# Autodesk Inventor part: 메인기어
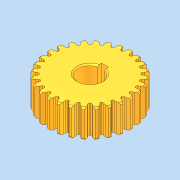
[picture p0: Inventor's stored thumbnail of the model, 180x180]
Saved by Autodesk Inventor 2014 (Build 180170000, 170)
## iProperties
Company: 한국ATC센터
Created: 2014-12
Part Number: 메인기어
Document SubType Name: Modeling
Designer: KYOUNG IL JANG
Density: 1 g/cm^3
Mass: 43.883 g
Surface Area: 122.661 cm^2
Volume: 43.883 cm^3
Material: 일반
Appearance: 금속 2400F 열
Author: KYOUNG IL JANG
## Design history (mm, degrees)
sketch "스케치1"
  geometry: C1 r 25.5 at (0, 0); A1 r 1.064 centre (-2.94, 26.392) between (-2.696, 25.357) and (-1.877, 26.361); A2 r 6.991 centre (5.094, 25.835) between (-1.626, 27.763) and (-1.877, 26.361); A3 r 11.864 centre (9.774, 24.478) between (-0.731, 29.991) and (-1.626, 27.763); A4 r 1.064 centre (2.94, 26.392) between (1.877, 26.361) and (2.696, 25.357); A5 r 6.991 centre (-5.094, 25.835) between (1.877, 26.361) and (1.626, 27.763); A6 r 11.864 centre (-9.774, 24.478) between (1.626, 27.763) and (0.731, 29.991); A7 r 25.5 centre (0, 0) between (2.696, 25.357) and (-2.696, 25.357); A8 r 30 centre (0, 0) between (0.731, 29.991) and (-0.731, 29.991); 1 further point
  constraints: 16 point on circle, 9 centre point, 2 coincident, 1 concentric
extrude "돌출1" new body sketch "스케치1" stored distance "d0" = 20; taper "d1" = 0 deg
extrude "돌출2" join sketch "스케치1" stored distance "d2" = 20; taper "d3" = 0 deg
chamfer "모따기1" distance "d4" = 1; stored, may be unused: second distance "d5" = 2, angle "d6" = 45 deg
hole "구멍1" diameter "d12" = 17; stored, may be unused: countersink angle "d16" = 90 deg, drill point angle "d18" = 118 deg; dims "d10" = 10, "d11" = 10, "d13" = 6, "d14" = 4, "d15" = 2, "d17" = 8
sketch "스케치2"
  geometry: L1 (-2.5, 8.124)-(-2.5, 10.8); L2 (-2.5, 10.8)-(2.5, 10.8); L3 (2.5, 10.8)-(2.5, 8.124); A1 r 8.5 centre (0, 0) between (-2.5, 8.124) and (2.5, 8.124) reference; 1 further point
  constraints: 6 end point, 2 parallel, 2 point on circle, 1 perpendicular, 1 vertical
  dimensions: "d19" = 5 distance of L1.end L2.end; "d20" = 2.3 distance edge to line of A1 L2
extrude "돌출3" cut sketch "스케치2" stored distance "d21" = 20; taper "d22" = 0 deg
chamfer "모따기2" distance "d23" = 1; stored, may be unused: second distance "d24" = 2, angle "d25" = 45 deg
node "솔리드1"
pattern_circular "원형 패턴1" dims angle "d8" = 360 deg
